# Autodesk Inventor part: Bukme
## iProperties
Shininess: 64.0
Length Units: 11269
Angle Units: 11279
Time Units: 11290
Mass Units: 11283
Length Display Precision: 3
Angle Display Precision: 2
Compacted: True
Part Number: Bukme
Document SubType Name: Sheet Metal
Created: 2003-09
Material: Stainless Steel, 440C
Designer: Ronald Myers
Manufacturer: Standard
Standards Organization: Custom
Density: 1 g/cm^3
Sheet Metal Rule: 1.0 mm Stainless
Density: 0.0
Volumn: 0.0
Area: 0.0
PropertySet Name: Model Information
Control State: 0
Master: False
Checked Out: False
Author: Ronald Myers
